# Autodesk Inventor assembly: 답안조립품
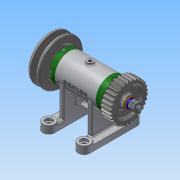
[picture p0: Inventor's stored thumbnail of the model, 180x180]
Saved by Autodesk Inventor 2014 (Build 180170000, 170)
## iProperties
Created: 2015-11
Part Number: 답안조립품
Document SubType Name: Assembly
Designer: 103-24
Author: 103-24
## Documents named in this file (15)
- C:\Users\103-24\Desktop\451110V1017\답안조립품.iam
- C:\Users\103-24\Desktop\451110V1017\1-본체.ipt
- C:\Users\103-24\Desktop\451110V1017\베어링 15 x 32 x 9.ipt
- C:\Users\103-24\Desktop\451110V1017\커버.ipt
- C:\Users\103-24\Desktop\451110V1017\오일 실 15 25 7.ipt
- C:\Users\103-24\Desktop\451110V1017\축.ipt
- C:\Users\103-24\Desktop\451110V1017\키 3 x 3 x 12.ipt
- C:\Users\103-24\Desktop\451110V1017\스퍼기어.ipt
- C:\Users\103-24\Desktop\451110V1017\와셔 8x17.ipt
- C:\Users\103-24\Desktop\451110V1017\스프링와셔 8.ipt
- C:\Users\103-24\Desktop\451110V1017\너트 M 8.ipt
- C:\Users\103-24\Desktop\451110V1017\V벨트풀리.ipt
- C:\Users\103-24\Desktop\451110V1017\와셔 6x11.5.ipt
- C:\Users\103-24\Desktop\451110V1017\볼트 M 6 x 8.ipt
- C:\Users\103-24\Desktop\451110V1017\볼트 M4 x 12.ipt
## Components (12 placed, 4 different names)
1. 1-본체:1
2. KS B 2023 6002 - 15 x 32 x 9:1
3. KS B 2023 6002 - 15 x 32 x 9:2
4. V벨트풀리:1 — 각도:4
5. ISO 4762 M4 x 12:1
6. ISO 4762 M4 x 12:3
7. ISO 4762 M4 x 12:4
8. ISO 4762 M4 x 12:5
9. ISO 4762 M4 x 12:2
10. ISO 4762 M4 x 12:6
11. ISO 4762 M4 x 12:7
12. ISO 4762 M4 x 12:8
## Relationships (1: Angle 1)
- 각도:4 [Angle]: V벨트풀리:1
